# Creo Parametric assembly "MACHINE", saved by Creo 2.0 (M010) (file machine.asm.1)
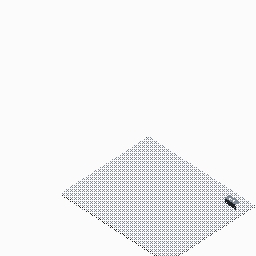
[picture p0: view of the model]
Units: Inch lbm Second (Pro/E Default); INCH, POUND, SECS

Created from: INLBS_ASM_DESIGN.ASM

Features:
  1. datum plane "ASM_RIGHT"
  2. datum plane "ASM_TOP"
  3. datum plane "ASM_FRONT"
  4. coordinate system
  5. component "YMOTOR"
  6. coordinate system
  7. component "BASE_BOARD"

Other named items: ACS0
